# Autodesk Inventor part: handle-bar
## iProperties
Author: Administrator
Created: 2001-03
Part Number: handle-bar
Document SubType Name: Modeling
Designer: Administrator
Control State: 0
Master: False
Checked Out: False
PropertySet Name: Design Tracking Control
Shininess: 5.0
PropertySet Name: _Private Model Information
Density: 0.0
Volumn: 0.0
Area: 0.0
PropertySet Name: Model Information
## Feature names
1. Sweep1
2. Extrusion1
3. Mirror1
